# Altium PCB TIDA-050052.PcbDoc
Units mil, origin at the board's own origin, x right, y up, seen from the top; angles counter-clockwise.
Board outline 779 x 852 mil, 4 copper layers (Top Layer, Signal Layer 1, Signal Layer 2, Bottom Layer), stack 40 mil thick; 22 components, 8 nets, 35 pads, 215 vias.
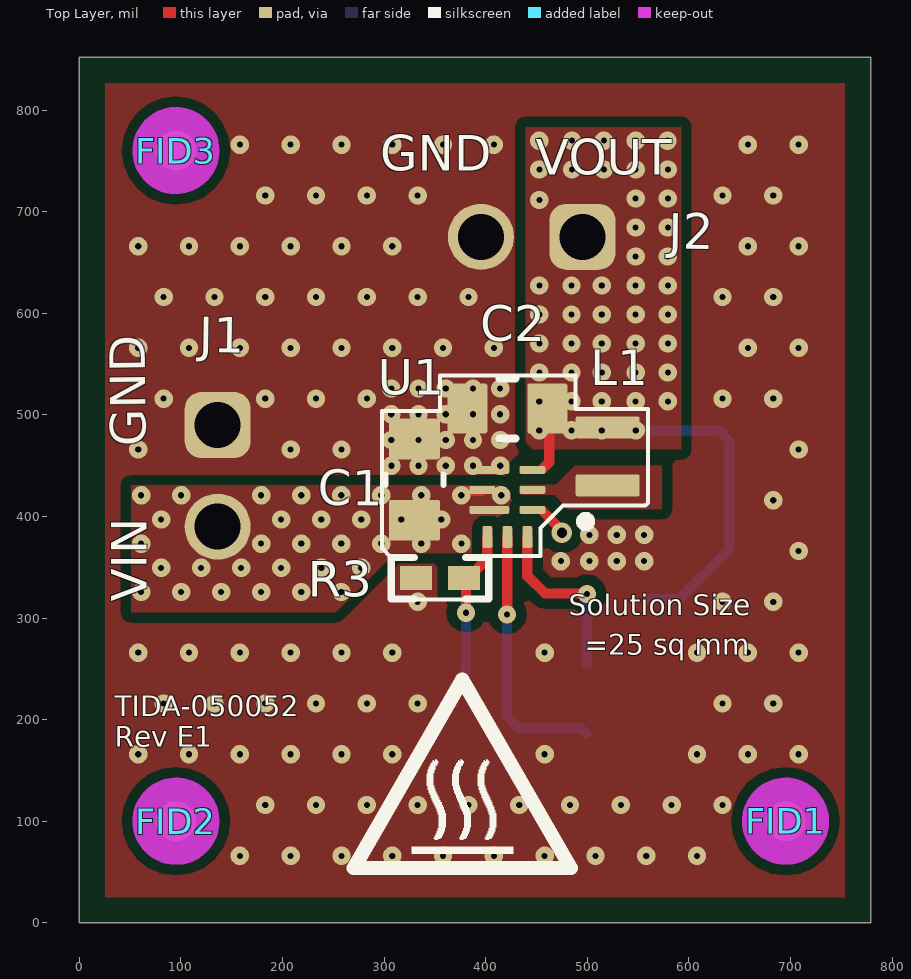
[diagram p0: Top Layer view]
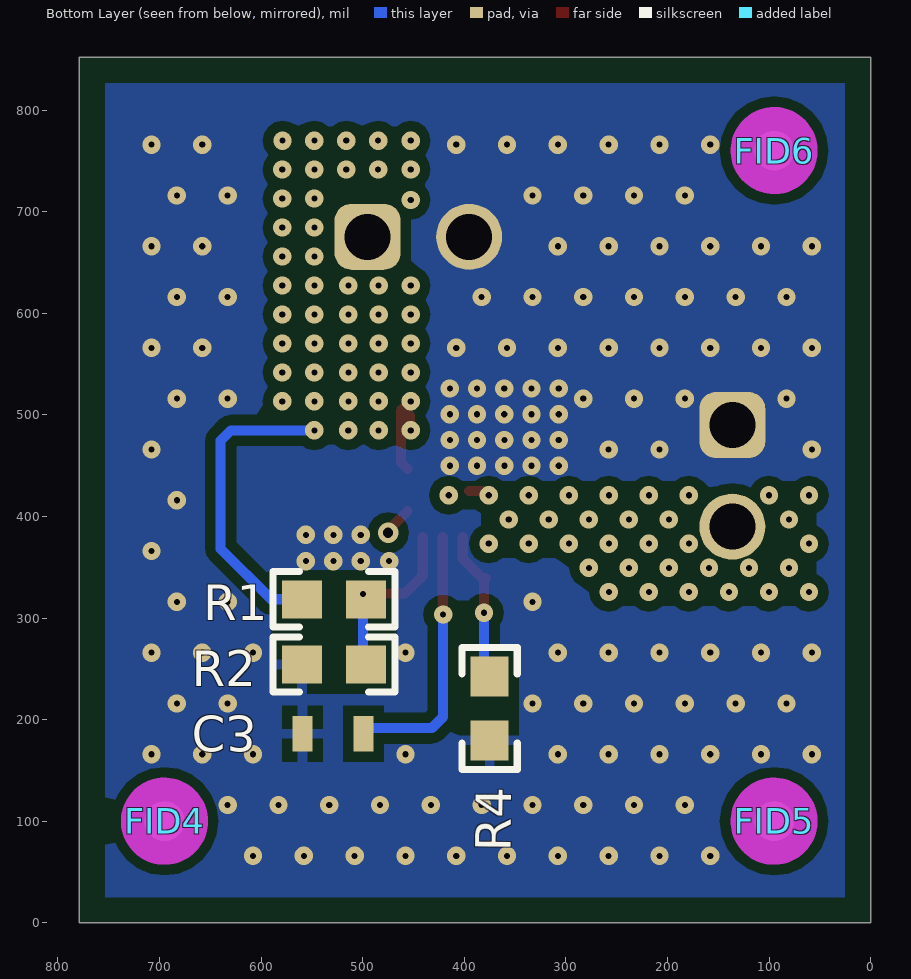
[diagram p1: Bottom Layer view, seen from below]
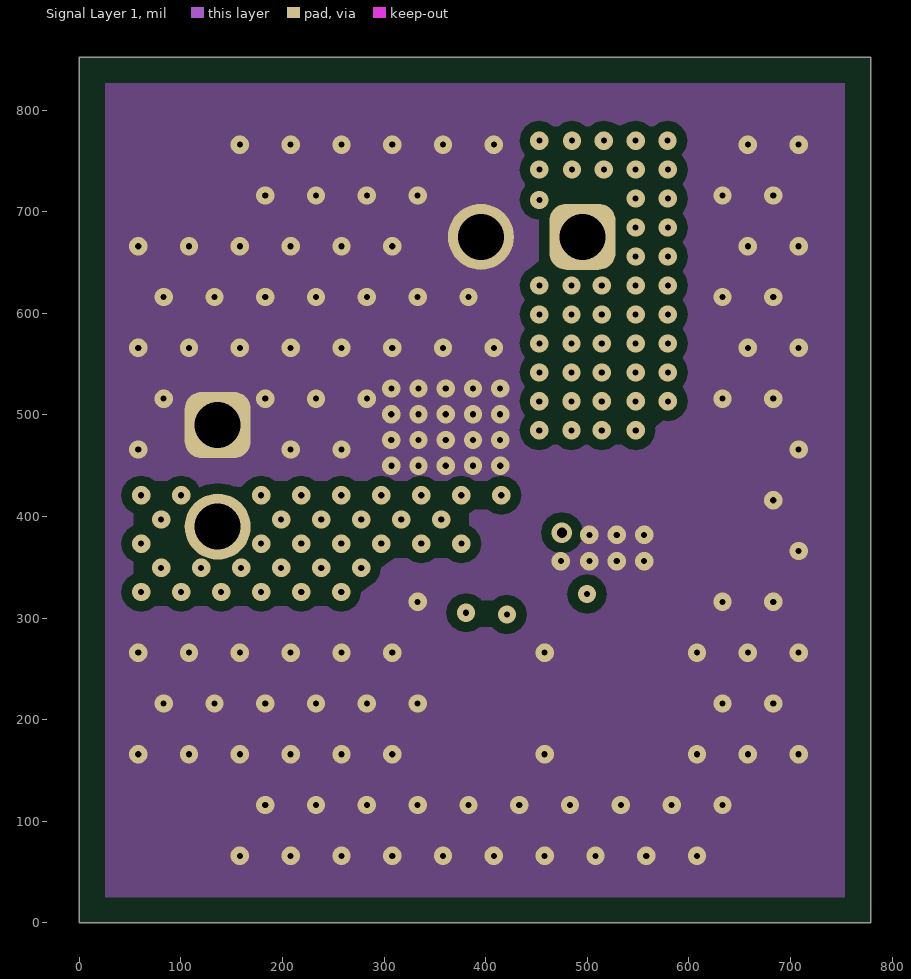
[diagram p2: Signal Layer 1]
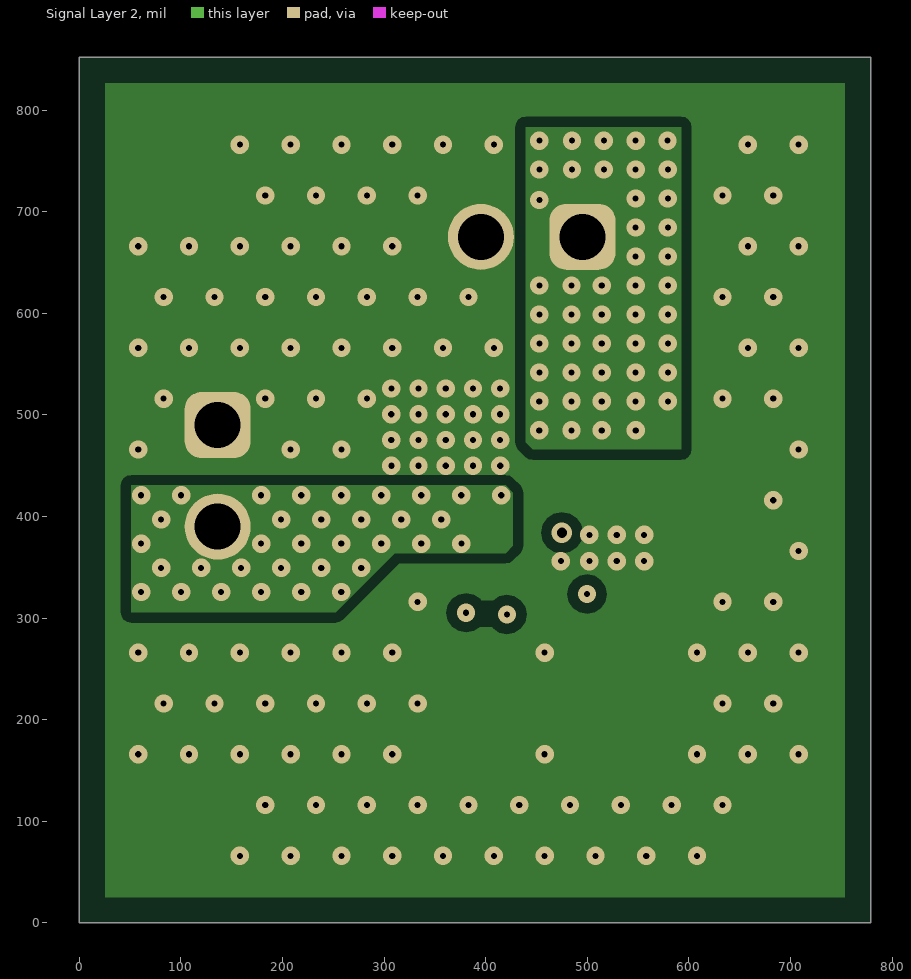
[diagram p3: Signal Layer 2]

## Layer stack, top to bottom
Top Solder: solder mask 0.4, Solder Resist, Dk 3.5
Top Layer: signal copper 1.4
Dielectric 1: prepreg 5, FR-4 High Tg, Dk 4.2
Signal Layer 1: signal copper 1.4
Dielectric 2: core 24.4, FR-4 High Tg, Dk 4.2
Signal Layer 2: signal copper 1.4
Dielectric 3: prepreg 5, FR-4 High Tg, Dk 4.2
Bottom Layer: signal copper 1.4
Bottom Solder: solder mask 0.4, Solder Resist, Dk 3.5

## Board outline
0,0 779,0 779,852 0,852

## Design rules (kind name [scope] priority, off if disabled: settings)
AcuteAngle [All] p1: minimum=4.50000000000000E+0001 checktracksonly=FALSE
AssemblyTestPointUsage [All] p1: valid=2
BoardOutlineClearance BoardOutlineClearance_MountingHoles [OnCopper and InComponentClass('Mounting Holes')] p1: gap=40 ignorepadtopadclearanceinfootprint=FALSE
BoardOutlineClearance BoardOutlineClearance_Poly [OnCopper and IsPoly] p2: gap=25 ignorepadtopadclearanceinfootprint=FALSE
BoardOutlineClearance [OnCopper and Not InComponentClass('Logo') and not InComponentClass('FiducialMark') and not InRegion(1000,500,4000,800) and not InPoly] p3: gap=40 ignorepadtopadclearanceinfootprint=FALSE
Clearance Clearance_BGA_Room [WithinRoom('BGA_Room')] p1: gap=5.9 ignorepadtopadclearanceinfootprint=FALSE
Clearance Clearance_Keepouts [((IsTrack Or IsArc) And Not InPoly) And IsFree and IsKeepOut vs ((IsTrack Or IsArc) And Not InPoly) And IsFree and IsKeepOut] p2: gap=0 ignorepadtopadclearanceinfootprint=FALSE
Clearance Clearance_Poly [InPolygon] p3: gap=10 ignorepadtopadclearanceinfootprint=FALSE
Clearance Clearance_FiducialMark [IsKeepOut and InComponentClass('FiducialMark') vs IsPad and InComponentClass('FiducialMark')] p4: gap=0 ignorepadtopadclearanceinfootprint=FALSE
Clearance [All] p5: gap=7.87 ignorepadtopadclearanceinfootprint=FALSE
ComponentClearance ComponentClearance_MountingHoles_FiducialMarks [InComponentClass('Mounting Holes') vs InComponentClass('FiducialMark')] p1: gap=50 collisioncheckmode=3 verticalgap=10 showdistances=FALSE
ComponentClearance ComponentClearance_Shunt [InComponentClass('Header') vs InComponentClass('Shunt')] p2: gap=0 collisioncheckmode=3 verticalgap=0 showdistances=FALSE
ComponentClearance ComponentClearance_Logo [InComponentClass('Logo')] p3: gap=30 collisioncheckmode=3 verticalgap=10 showdistances=FALSE
ComponentClearance ComponentClearance_ScrewToNut [(HasFootprint('NY PMS 440 0025 PH')) vs (HasFootprint('Keystone_1902C'))] p4: gap=5 collisioncheckmode=3 verticalgap=10 showdistances=FALSE
ComponentClearance ComponentClearance_MountingHoles [InComponentClass('Mounting Holes')] p5: gap=100 collisioncheckmode=3 verticalgap=100000 showdistances=FALSE
ComponentClearance ComponentClearance_SmallPassives [HasFootprint('0201*') or HasFootprint('0402*') or HasFootprint('0508') or HasFootprint('0603*') or HasFootprint('0612') or HasFootprint('0805*') or HasFootprint('0815*') or HasFootprint('0830*') or HasFootprint('1206*') or HasFootprint('1210*') or HasFootprint('1808*') or HasFootprint('1812*') or HasFootprint('1825*') or HasFootprint('2010*') or HasFootprint('2220*') or HasFootprint('2225*') or HasFootprint('2512*') or HasFootprint('2728*') or HasFootprint('3518*') vs HasFootprint('0201*') or HasFootprint('0402*') or HasFootprint('0508') or HasFootprint('0603*') or HasFootprint('0612') or HasFootprint('0805*') or HasFootprint('0815*') or HasFootprint('0830*') or HasFootprint('1206*') or HasFootprint('1210*') or HasFootprint('1808*') or HasFootprint('1812*') or HasFootprint('1825*') or HasFootprint('2010*') or HasFootprint('2220*') or HasFootprint('2225*') or HasFootprint('2512*') or HasFootprint('2728*') or HasFootprint('3518*')] p6: gap=14.96 collisioncheckmode=3 verticalgap=10 showdistances=FALSE
ComponentClearance ComponentClearance_THtoSMT [IsThruComponent vs IsSMTComponent] p7: gap=30 collisioncheckmode=3 verticalgap=30 showdistances=FALSE
ComponentClearance ComponentClearance_THtoTH [IsThruComponent vs IsThruComponent] p8: gap=30 collisioncheckmode=3 verticalgap=30 showdistances=FALSE
ComponentClearance [All] p9: gap=20 collisioncheckmode=3 verticalgap=10 showdistances=FALSE
DiffPairsRouting [All] p1: maxlimit=100 minlimit=10 mostfreqgap=10 toplayer_minwidth=15 toplayer_maxwidth=15 toplayer_prefwidth=15 midlayer1_minwidth=15 midlayer1_maxwidth=15 midlayer1_prefwidth=15 midlayer2_minwidth=15 midlayer2_maxwidth=15 midlayer2_prefwidth=15 bottomlayer_minwidth=15 bottomlayer_maxwidth=15 bottomlayer_prefwidth=15 maxuncoupledlength=1000
FabricationTestPointUsage TestPointUsage [All] p1: valid=2 allowmultiple=FALSE
FabricationTestpoint Testpoint [All] p1: side=3 testpointundercomponent=TRUE minsize=40 maxsize=100 preferedsize=60 minholesize=0 maxholesize=40 preferedholesize=32 testpointgrid=1 allowsidetop=TRUE allowsidebottom=TRUE usegrid=TRUE gridtolerance=0.01
FanoutControl Fanout_LCC [IsLCC] p1: bgadir=Out bgaviamode=Centered fanoutstyle=Auto fanoutdirection=Alternating viagrid=1 // Fanout_LCC (Default Rule)
FanoutControl Fanout_BGA [IsBGA] p2: bgadir=Out bgaviamode=Centered fanoutstyle=Auto fanoutdirection=Alternating viagrid=1 // Fanout_BGA (Default Rule)
FanoutControl Fanout_Default [All] p4: bgadir=Out bgaviamode=Centered fanoutstyle=Auto fanoutdirection=Alternating viagrid=1 // Fanout_Default (Default Rule)
FanoutControl Fanout_Small [(CompPinCount < 5)] p5: bgadir=Out bgaviamode=Centered fanoutstyle=Auto fanoutdirection=OutThenIn viagrid=1 // Fanout_Small (Default Rule)
HoleSize [All] p1: absolutevalues=TRUE maxlimit=251 minlimit=5.9 maxpercent=80.000 minpercent=20.000
MinimumAnnularRing MinimumAnnularRing_ThermalPadVias [IsVia and InAnyComponent] p1: minimumring=5.91
MinimumAnnularRing [All] p2: minimumring=5
MinimumSolderMaskSliver MinimumSolderMaskSliver_Logo [InComponentClass('Logo') vs InComponentClass('Logo')] p1: minsoldermaskwidth=0.7
MinimumSolderMaskSliver [All] p2: minsoldermaskwidth=3.94
PlaneConnect [All] p1: planeconnectstyle=Relief reliefexpansion=10 reliefentries=4 reliefconductorwidth=10 reliefairgap=10
PolygonConnect PolygonConnect_R2 [InComponent('R4') or InComponent('C3') or InComponent('R2') or InComponent('R6') or InComponent('R8')] p1: connectstyle=Relief reliefconductorwidth=10 reliefentries=4 polygonreliefangle="90 Angle" airgapwidth=10
PolygonConnect [All] p2: connectstyle=Direct reliefconductorwidth=10 reliefentries=4 polygonreliefangle="90 Angle" airgapwidth=10
RoomDefinition BGA_Room [False] p1: confinementstyle=ConfineIn formatcopy=TRUE lockcomponents=FALSE outline 1079,796 1265,796 1265,610.65 1079,610.65
RoutingVias ThermalPadVias [IsVia and InAnyComponent] p1: holewidth=7.87 width=19.68 viastyle="Through Hole" minholewidth=7.87 minwidth=19.68 maxholewidth=12.99 maxwidth=23.62
RoutingVias [All] p2: holewidth=16 width=34 viastyle="Through Hole" minholewidth=5.9 minwidth=18 maxholewidth=40 maxwidth=65
SilkToBoardRegionClearance [Not ((IsComment or IsDesignator) And (Hide <> 'False')) and not InRegion(1000,500,4000,800)] p1:
SilkToSilkClearance SilkToSilkClearance_Pb-FreeLogo [(HasFootprint('Pb-Free_Overlay_Medium') OR HasFootprint('Pb-Free_Overlay_Small')) vs (HasFootprint('Pb-Free_Overlay_Medium') OR HasFootprint('Pb-Free_Overlay_Small'))] p1: silktosilkclearance=0
SilkToSilkClearance [All] p2: silktosilkclearance=4
SilkToSolderMaskClearance SilkToComponentPadClearance [(IsPad or IsFill or IsRegion) and InAnycomponent] p1: minsilkscreentomaskgap=5 clearancetoexposedcopper=TRUE
SilkToSolderMaskClearance "Silk to Solder Mask Opening" [All] p2: minsilkscreentomaskgap=3.94 clearancetoexposedcopper=FALSE
SolderMaskExpansion [All] p1: expansion=1.97
Width [All] p1: maxlimit=100 minlimit=6 preferedwidth=10 checkconnectedcopper=TRUE
15 further rules are at their usual default settings.

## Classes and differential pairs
component class TIDA-050052_Hardware: FID1 FID2 FID3 FID4 FID5 FID6 SH-J1 SH-J5 ZZ1 ZZ2 ZZ3 ZZ4
component class FiducialMark: FID1 FID2 FID3 FID4 FID5 FID6
component class AssemblyNote: ZZ1 ZZ2 ZZ3 ZZ4
component class TIDA-050052: C1 C2 C3 J1 J2 L1 R1 R2 R3 R4 R49 U1
component class Header: J1 J2

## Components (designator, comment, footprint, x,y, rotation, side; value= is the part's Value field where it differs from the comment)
C1 "GMC21X7R106K25NT" FP-GMC21X7R106K25NT_0805-MFG 330,436.32 r270 top value=10µF
C2 "C2012X7S1A226M125AC" 0805_HV1 421.26,506.34 r180 top value=22uF
C3 "GRM1885C1H332JA01D" 0603S 529.26,186.34 r0 bottom value=3300pF
FID1 "Fiducial" Fiducial10-20 695.13,100.14 r0 top
FID2 "Fiducial" Fiducial10-20 95.13,100.14 r0 top
FID3 "Fiducial" Fiducial10-20 95.13,760.14 r0 top
FID4 "Fiducial" Fiducial10-20 695.13,100.14 r90 bottom
FID5 "Fiducial" Fiducial10-20 95.13,100.14 r180 bottom
FID6 "Fiducial" Fiducial10-20 95.13,760.14 r180 bottom
J1 "61300211121" WURTH_61300211121 136.26,440.05 r270 top
J2 "61300211121" WURTH_61300211121 445.26,675.34 r180 top
L1 "DFE201612E-1R0M=P2" DFE201612E 520.07,459.11 r90 top value=1uH
R1 "RC0603FR-0726K1L" 0603 528.26,318.54 r0 bottom value=26.1k
R2 "RC0603JR-070RL" 0603 528.26,254.34 r180 bottom value=0
R3 "CRCW040226K1FKED" 0402 355,339.34 r0 top value=26.1k
R4 "RC0603FR-0726K1L" 0603 375.13,211.14 r90 bottom value=26.1k
U1 "TPS62903RPJR" RPJ0009A 421.26,416.34 r180 top
ZZ1 "This Assembly Note is for PCB labels only" AssemblyNoteLabel 0,2000 r0 top
ZZ2 "These assemblies are ESD sensitive, ESD precautions shall be observed." AssemblyNote 0,1900 r0 top
ZZ3 "These assemblies must be clean and free from flux and all contaminants. Use of no clean flux is not acceptable." AssemblyNote 0,1800 r0 top
ZZ4 "These assemblies must comply with workmanship standards IPC-A-610 Class 2, unless otherwise specified." AssemblyNote 0,1700 r0 top
? "CAUTION HOT SURFACE" IEC_HotSurface_Small 377,147 r0 top

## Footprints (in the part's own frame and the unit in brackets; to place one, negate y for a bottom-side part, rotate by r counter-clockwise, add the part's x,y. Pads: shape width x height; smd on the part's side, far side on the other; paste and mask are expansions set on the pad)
0402 [mm] "0402 from SM-752 data"
  rect 0.8x0.6 smd: 1(-0.6,0) 2(0.6,0)
  silkscreen extent -1.22,-0.52 1.22,0.52, body extent -0.55,-0.3 0.55,0.3, height 0.6
0603 [mm] "0603 from SM-752 data"
  rect 1x0.95 smd: 1(-0.8,0) 2(0.8,0)
  silkscreen extent -1.52,-0.69 1.52,0.69, body extent -0.87,-0.47 0.87,0.47, height 1
0603S [mil]
  rect 20x35 smd: 1(-30,0) 2(30,0)
  body extent -34,-19 34,19, height 39
0805_HV1 [mm] "Custom footprint based on analyzing multiple manufacturer recommendations"
  rrect10% 1x1.25 smd: 1(-1,0) 2(1,0)
  silkscreen extent -0.2,-0.75 0.2,0.75, body extent -1.1,-0.72 1.1,0.73, height 1.45
AssemblyNote [mil] "Assembly Note"
AssemblyNoteLabel [mil] "Assembly Note for PCB Labels"
DFE201612E [mm] "MuRata recommended"
  rrect18% 0.55x1.6 smd: 1(-0.725,0) 2(0.725,0)
  body extent -1.1,-0.9 1.1,0.9, height 1.2
Fiducial10-20 [mm]
  round 1 smd mask+0.5: 1(0,0)
  Top Layer keep-out circle w1.178: c0,0 r0.5
FP-GMC21X7R106K25NT_0805-MFG [mil]
  rrect10% 40x50 smd paste+0 mask+0: 1(-40,0) 2(40,0)
  silkscreen extent -5,-29 5,29, body extent -64,-32 64,32, height 10
IEC_HotSurface_Small [mil]
  silkscreen extent -107,-93 107,92
RPJ0009A [mm] "VQFN-HR-9"
  rrect50% 0.65x0.2 smd: 1(-0.625,0.25) 2(-0.625,-0.25) 3(-0.625,-0.75) 5(0.625,-0.25)
  rrect50% 1x0.2 smd: 4(0.45,-0.75) 6(0.45,0.25)
  rrect40% 0.25x0.55 smd: 7(0.5,0.925) 8(0,0.925) 9(-0.5,0.925)
  body extent -0.8,-1.05 0.8,1.05, height 1
WURTH_61300211121 [mm] "Header, 2.54mm, 2x1, TH"
  rrect50% 1.65x1.65 hole 1.15: 1(-1.27,0)
  round 1.65 hole 1.15: 2(1.27,0)
  body extent -2.54,-1.27 2.54,1.27, height 8.54

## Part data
C1: library part CMP-0092369-1, "CAP0805 X7R 10UF 10% 25V", Manufacturer="Cal-Chip Electronics", Operating Temperature Range="-55°C to +125°C", TempCo=15%, Temperature Characteristic=X7R, Tolerance_%=10%, ValueDisplayed=10uF
C2: library part CMP-0007890-2, "CAP, CERM, 22 uF, 10 V, +/- 20%, X7S, 0805", Cap_Case=0805, Manufacturer=TDK, Supplier Part Number 1=445-14560-1-ND, TempCo=X7S, Tolerance_%=20%, Value1="0.00205 ohm", Value2=10V, ValueDisplayed=22uF
C3: library part CMP-0007210-4, "CAP, CERM, 3300 pF, 50 V, +/- 5%, C0G/NP0, 0603", Cap_Case=0603, Manufacturer=MuRata, Supplier Part Number 1=GRM1885C1H332JA01D-ND, TempCo=C0G/NP0, Tolerance_%=5%, Value1=Unknown, Value2=50V, ValueDisplayed=3300pF
FID1 FID2 FID3 FID4 FID5 FID6: library part CMP-0077181-1, "Fiducial mark.  There is nothing to buy or mount.", Manufacturer=N/A
J1 J2: library part CMP-0054794-2, "Header, 2.54 mm, 2x1, Gold, TH", Color=Black, Manufacturer="Wurth Elektronik", Supplier Part Number 1=732-5315-ND
L1: library part CMP-0080773-1, "Inductor, Shielded, Metal Composite, 1 µH, 2.9 A, 0.048 ohm, SMD", Manufacturer=MuRata, PartNumber=DFE201612E-1R0M{}P2, Value1="0.048 ohm", Value2=2.9A, ValueDisplayed=1µH
R1 R4: library part CMP-0022957-2, "RES, 26.1 k, 1%, 0.1 W, 0603", Manufacturer="Yageo America", Power_W=100mW, Supplier Part Number 1=311-26.1KHRCT-ND, TempCo="200 ppm/C", Tolerance_%=1%, Value2=0.1W, Value_Code=26k1, ValueDisplayed=26.1k
R2: library part CMP-0025885-1, "RES, 0, 5%, 0.1 W, 0603", Manufacturer="Yageo America", Power_W=100mW, Supplier Part Number 1=311-0.0GRCT-ND, TempCo="200 ppm/C", Tolerance_%=5%, Value2=0.1W, Value_Code=0000, ValueDisplayed=0
R3: library part CMP-0026207-1, "RES, 26.1 k, 1%, 0.063 W, 0402", Manufacturer=Vishay-Dale, Power_W=63mW, Supplier Part Number 1=541-26.1KLCT-ND, TempCo="100 ppm/C", Tolerance_%=1%, Value2=0.063W, Value_Code=26k1, ValueDisplayed=26.1k
U1: library part CMP-0084866-4, "2.9-V to 18-V, 3-A Synchronous Buck Converters, RPJ0009A (VQFN-HR-9)", Alternate Manufacturer="Texas Instruments", Alternate PartNumber=TPS62903RPJT
ZZ1: library part CMP-0003616-3
ZZ2: library part CMP-0077236-1
ZZ3: library part CMP-0077237-1
ZZ4: library part CMP-0077238-1
?: library part CMP-0074837-1, "IEC 61010-1 Hot Surface Warning"

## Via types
v1: diameter 18, hole 6, Top Layer to Bottom Layer, tented both sides, 192 vias
v2: diameter 18, hole 6.1, Top Layer to Bottom Layer, tented both sides, 22 vias
v3: diameter 20, hole 10, Top Layer to Bottom Layer, 1 vias

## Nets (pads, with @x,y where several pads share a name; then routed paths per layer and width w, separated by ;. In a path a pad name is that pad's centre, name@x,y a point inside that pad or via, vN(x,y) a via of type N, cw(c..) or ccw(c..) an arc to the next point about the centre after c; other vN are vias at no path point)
GND: C1.1 C2.2 C3.2 J1.1 J2.2 R2.1 R3.1 R4.1 U1.4
  other v1: 158,66 208,66 258,66 308,66 358,66 408,66 458,66 508,66 558,66 608,66 183,116 233,116 283,116 333,116 383,116 433,116 483,116 533,116 583,116 633,116 58,166 108,166 158,166 208,166 258,166 308,166 458,166 608,166 658,166 708,166 83,216 133,216 183,216 233,216 283,216 333,216 633,216 683,216 58,266 108,266 158,266 208,266 258,266 308,266 458,266 608,266 658,266 708,266 333,316 633,316 683,316 474,356.06 502,356.06 529,356.06 556,356.06 708,366 502,382 529,382 556,382 683,416 307.1,450 333.89,450 360.68,450 58,466 208,466 258,466 708,466 360.68,475.32 387.47,475.32 414.26,475.32 414.26,500.64 83,516 183,516 233,516 283,516 633,516 683,516 307.1,525.97 333.89,525.97 414.26,525.97 58,566 108,566 158,566 208,566 258,566 308,566 358,566 408,566 658,566 708,566 83,616 133,616 183,616 233,616 283,616 333,616 383,616 633,616 683,616 58,666 108,666 158,666 208,666 258,666 308,666 658,666 708,666 183,716 233,716 283,716 333,716 633,716 683,716 158,766 208,766 258,766 308,766 358,766 408,766 658,766 708,766
  other v2: 387.47,450 414.26,450 307.1,475.32 333.89,475.32 307.1,500.64 333.89,500.64 360.68,500.64 387.47,500.64 360.68,525.97 387.47,525.97
NetC2_1: C2.1 J2.1 L1.2 R1.2 U1.3 | length 391.2
  Top Layer w10: C2.1@453.66,484.82 453.66,499.37 C2.1 462.51,504.45 462.51,453.49 U1.3@456.04,447.02
  Bottom Layer w10: v2@547.26,484.82 v2(547.63,484.82) 629.78,484.82 639.95,474.65 639.95,368.34 590.15,318.54 R1.2
  other v1: 514.21,513.34 547.63,513.34 579.26,513.34 452.75,541.86 484.38,541.86 514.21,541.86 547.63,541.86 579.26,541.86 452.75,570.37 484.38,570.37 514.21,570.37 547.63,570.37 579.26,570.37 452.75,598.89 484.38,598.89 514.21,598.89 547.63,598.89 579.26,598.89 452.75,627.41 484.38,627.41 514.21,627.41 547.63,627.41 579.26,627.41 547.63,655.93 579.26,655.93 547.63,684.45 579.26,684.45 452.75,711.62 547.63,712.96 579.26,712.96 452.75,741.48 484.89,741.48 516.26,741.48 547.63,741.48 579.26,741.48 452.75,770 484.89,770 516.26,770 547.63,770 579,770
  other v2: 452.75,484.82 484.38,484.82 514.21,484.82 452.75,513.34 484.38,513.34
NetC3_1: C3.1 U1.8 | length 262.4
  Top Layer w10: v1(420.88,303.6) 421.26,303.98 U1.8
  Bottom Layer w10: v1(420.88,303.6) 420.88,202.95 432.08,191.75 493.84,191.75 C3.1
NetR1_1: R1.1 R2.2 U1.9 | length 165.7
  Top Layer w10: U1.9 440.94,341.73 458.34,324.34 v1@495.76,324.34
  Bottom Layer w10: R1.1 499.76,315.54 R2.2@499.76,254.34
  other v1: 499.76,323.67
NetR3_2: R3.2 R4.2 U1.7 | length 152.3
  Top Layer w10: v1(380.7,305.28) 380.7,337.26 R3.2 382.56,339.34 401.57,358.35 U1.7
  Bottom Layer w10: R4.2 380.7,248.21 v1(380.7,305.28)
PG: U1.1 | length 31
  Top Layer w10: U1.1@455.83,405.45 474,387.28 v3@474,382
  other v3: 475,384
SW: L1.1 U1.2
VIN: C1.2 J1.2 U1.5 U1.6 | length 21.3
  Top Layer w10: v2(376,420.96) 378.16,420.96 382.32,425.12 U1.5@395.59,425.12
  other v1: 60.83,325.71 100.23,325.71 139.62,325.71 179.02,325.71 218.42,325.71 257.81,325.71 80.53,349.53 119.93,349.53 159.32,349.53 198.72,349.53 238.11,349.53 277.51,349.53 60.83,373.34 179.02,373.34 218.42,373.34 257.81,373.34 297.21,373.34 376,373.34 80.53,397.15 198.72,397.15 238.11,397.15 277.51,397.15 60.83,420.96 100.23,420.96 179.02,420.96 218.42,420.96 257.81,420.96 297.21,420.96
  other v2: 336.6,373.34 316.91,397.15 356.3,397.15 336.6,420.96 415.4,420.96
pads on no net: FID1.1 FID2.1 FID3.1 FID4.1 FID5.1 FID6.1

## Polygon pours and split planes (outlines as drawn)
GND on Top Layer "TOP_LAYER_GND_P036" (solid, remove dead copper, pour order 36): 1,852.83 780,852.83 780,0.83 1,0.83
VIN on Top Layer "TOP_LAYER_VIN_P033" (solid, remove dead copper, pour order 33): 51,430.67 51,305.64 252.17,305.64 310.53,364 426.63,364 426.63,430.67
SW on Top Layer "TOP_LAYER_SW_P030" (solid, remove dead copper, pour order 30): 434.63,431.34 469.14,431.34 487.77,449.94 573.26,449.94 573.26,407.34 481.26,407.34 467.26,421.34 434.63,421.34
NetC2_1 on Top Layer "TOP_LAYER_NETC2_1_P032" (solid, remove dead copper, pour order 32): 592.26,466 592.26,783.34 439.26,783.34 439.26,508.34 439.26,466
GND on Signal Layer 2 "SIGNAL_LAYER_2_GND_P046" (solid, remove dead copper, pour order 46): 0,852 779,852 779,2.34 0,2.34
VIN on Signal Layer 2 "SIGNAL_LAYER_2_VIN_P044" (solid, remove dead copper, pour order 44): 252.17,305.64 310.53,364 426.63,364 426.63,430.67 51,430.67 51,305.64
NetC2_1 on Signal Layer 2 "SIGNAL_LAYER_2_NETC2_1_P042" (solid, remove dead copper, pour order 42): 446.33,466 592.26,466 592.26,783.34 439.26,783.34 439.26,473.07
GND on Bottom Layer "BOTTOM_LAYER_GND_P050" (solid, remove dead copper, pour order 50): 0.26,852 779,852 779,0 0.26,0
GND on Signal Layer 1 "SIGNAL_LAYER_1_GND_P040" (solid, remove dead copper, pour order 40): 1,852.83 780,852.83 780,2.16 1,2.17

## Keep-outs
Keep-Out Layer:
  text ".Layer_Name" at 577,-858.49 h60

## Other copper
Top Layer:
  pour cut-out: 329.36,462.34
  pour cut-out: 483.26,332.34
  pour cut-out: 642.36,452.34
  pour cut-out: 571.73,464 571.73,450.34 570.26,450.34 565.59,450.34 534.73,450.34 534.73,464
  pour cut-out: 624.26,457.34
  pour cut-out: 527.26,339.34
  text ".Layer_Name" at 577,-858.49 h60
Signal Layer 1:
  text ".Layer_Name" at 577,-857.49 h60
Signal Layer 2:
  text ".Layer_Name" at 577,-857.49 h60
Bottom Layer:
  text ".Layer_Name" at 577,-858.49 h60

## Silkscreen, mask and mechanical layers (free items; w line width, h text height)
Top Overlay:
  circle w10: c498.27,395.1 r4.47
  lines w4: 307,359.84 298,368.84 298,503.7 355,503.7 355,539 488.26,539 488.26,506 559.54,506 559.54,430.99 559.54,413.38 557.03,410.87 476.14,410.87 454,388.73 454,361 403,361 403,338.6 403,318.21 396.45,318.21 309.02,318.21
  text "GND" at 296.13,740.14 h35
  text "VOUT" at 449.26,736.34 h35
  text "GND" at 65.99,469.14 h35 r90.77
  text "VIN" at 66.26,316.34 h35 r90
  text "Solution Size" at 481.68,303 h20
  text "=25 sq mm" at 497.26,264.14 h20
  text "TIDA-050052 / Rev E1" at 35,173.48 h20
  text ".Layer_Name" at 577,-858.49 h60
Bottom Overlay:
  text ".Layer_Name" at 577,-858.49 h60
Top Paste:
  text ".Layer_Name" at 577,-858.49 h60
Bottom Paste:
  text ".Layer_Name" at 577,-858.49 h60
Top Solder:
  text ".Layer_Name" at 577,-858.49 h60
  text ".Layer_Name" at 577,-858.49 h60
Bottom Solder:
  text ".Layer_Name" at 577,-858.49 h60
Drill Guide:
  text ".Layer_Name" at 577,-858.49 h60
M1 Board Outline:
  lines w10: -5,0 ccw(c0,0) 0,-5 ; -5,0 ccw(c0,0) 0,-5 ; -5,0 -5,852 ; -5,852 cw(c0,852) 0,857 ; -5,852 cw(c0,852) 0,857 ; 0,-5 779,-5 ; 0,857 779,857 ; 779,-5 ccw(c779,0) 784,0 ; 779,-5 ccw(c779,0) 784,0 ; 779,857 cw(c779,852) 784,852 ; 779,857 cw(c779,852) 784,852 ; 784,0 784,852 ; 5,5 774,5 774,847 5,847 5,5 ; 26.23,31 752.77,31 752.77,822 26.23,822 26.23,31
  text ".Layer_Name" at 577,-858.49 h60
M2 Board Dimensions:
  rectangle: 0,-275 125,-150
  rectangle: 125,-400 500,-275
  lines w7: 0,-275 1000,-275 ; 125,-400 125,-150 ; 250,-400 250,-150 ; 500,-400 500,-150 ; 750,-400 750,-150 ; 0,-400 1000,-400 1000,-150 0,-150 0,-400
  text ".Layer_Name" at 577,-858.49 h60
M3 3D STEP Top:
  text ".Layer_Name" at 577,-858.49 h60
M4 3D STEP Bottom:
  text ".Layer_Name" at 577,-858.49 h60
M5 Assembly Top:
  lines w10: -292,-930.17 6308,-930.17 ; -292,-726.83 6310,-726.83 ; -292,-523.5 -292,-1133.5 3713,-1133.5 6310,-1133.5 6310,-523.5 -291.5,-523.5 -291.5,-1133.5 1284,-1133.5 ; 2173,-1133.5 2173,-523.5 ; 3440,-726.83 3440,-523.5 ; 4280,-726.83 4280,-523.5 ; 4902,-1140 4902,-937.17
  text "COMPONENTS MARKED 'DNP' SHOULD NOT BE POPULATED." at 1153.5,-318.5 h60
  text "ASSEMBLY VARIANT:" at 1153,-434 h60
  text ".VariantName" at 2189,-434 h60
  text "PCB VIEWED FROM TOP SIDE" at -228.5,-655.67 h60
  text "BOARD #:" at 2248,-655.67 h60
  text ".PRJ_Number" at 2793.5,-655.67 h60
  text "REV:" at 3638,-655.67 h60
  text ".PCB_Rev" at 3929.5,-655.67 h60
  text "SVN REV:" at 4476,-655.67 h60
  text ".VersionControl_RevNumber" at 4982,-655.67 h60
  text "TID #:" at 2248,-859 h60
  text ".TID" at 2793.5,-859 h60
  text "PLOT NAME =" at -228.5,-1064.34 h60
  text ".plot_File_Name" at 577,-1064.34 h60
  text "GENERATED    :" at 2250,-1064.34 h60
  text ".Print_Date" at 3119.5,-1064.34 h60
  text ".Print_Time" at 3848.5,-1064.34 h60
  text "TEXAS INSTRUMENTS" at 5113,-1064.34 h60
M6 Assembly Bottom:
  lines w10: -292.5,-727.33 6309.5,-727.33 ; -290.5,-930.67 6309.5,-930.67 ; 1115.5,-1140.5 1115.5,-937.67 ; 1737.5,-727.33 1737.5,-524 ; 2577.5,-727.33 2577.5,-524 ; 3844.5,-1134 3844.5,-524 ; 4733.5,-1134 6309,-1134 6309,-524 -292.5,-524 -292.5,-1134 2304.5,-1134 6309.5,-1134 6309.5,-524
  text "COMPONENTS MARKED 'DNP' SHOULD NOT BE POPULATED." at 6102,-318 h60
  text ".VariantName" at 5058,-434 h60
  text "ASSEMBLY VARIANT:" at 6097,-434 h60
  text ".VersionControl_RevNumber" at 1035.5,-656.17 h60
  text "SVN REV:" at 1541.5,-656.17 h60
  text ".PCB_Rev" at 2088,-656.17 h60
  text "REV:" at 2379.5,-656.17 h60
  text ".PRJ_Number" at 3224,-656.17 h60
  text "BOARD #:" at 3769.5,-656.17 h60
  text "PCB VIEWED FROM BOTTOM SIDE" at 6246,-656.17 h60
  text ".TID" at 3224,-859.5 h60
  text "TID #:" at 3769.5,-859.5 h60
  text "TEXAS INSTRUMENTS" at 904.5,-1064.84 h60
  text ".Print_Time" at 2169,-1064.84 h60
  text ".Print_Date" at 2898,-1064.84 h60
  text "GENERATED    :" at 3767.5,-1064.84 h60
  text ".plot_File_Name" at 5440.5,-1064.84 h60
  text "PLOT NAME =" at 6246,-1064.84 h60
M9 Title Sheet:
  drawing of 57 lines, arcs and shapes, not listed
  text "1" at 739.84,8036.5 h70
  text "2" at 3235.5,8036.5 h70
  text "3" at 5724.84,8036.5 h70
  text "4" at 8231.51,8036.5 h70
  text "5" at 10730.5,8036.5 h70
  text "6" at 13235.5,8036.5 h70
  text "A" at -416.5,6893.5 h70
  text "A" at 14383.5,6893.5 h70
  text "B" at -416.5,4513.5 h70
  text "B" at 14383.5,4513.5 h70
  text "C" at -416.5,2138.5 h70
  text "C" at 14383.5,2138.5 h70
  text "PROJECT TITLE:" at 11343.5,277.5 h45
  text ".PRJ_Title" at 11393.5,144.17 h70
  text "DESIGNED FOR:" at 11343.5,-23.5 h45
  text ".PRJ_Customer" at 11393.5,-163.5 h70
  text "D" at -416.5,-231.5 h70
  text "D" at 14383.5,-231.5 h70
  text "FILE NAME:" at 11343.5,-323.5 h45
  text ".PCB_File_Name_No_Path" at 11393.5,-443.5 h70
  text "Texas Instruments (TI) and/or its licensors do not warrant the accuracy or completeness of this specification" at 6374,-605.34 h45
  text "ENGINEER:" at 11343.5,-613.5 h45
  text "LAYOUT BY:" at 12848.5,-613.5 h45
  text "or any information contained therein. TI and/or its licensors do not warrant that this design will meet" at 6329.01,-718 h45
  text ".PRJ_Engineer" at 11393.5,-768.49 h70
  text ".PCB_Layout" at 12899,-768.49 h70
  text "the specifications, will be suitable for your application or fit for any particular purpose, or will operate in" at 6329.01,-830.67 h45
  text ".Layer_Name" at 577,-858.49 h60
  text "ALTIUM DESIGNER VERSION:" at 12848.5,-923.5 h45
  text "an implementation. TI and/or its licensors do not warrant that the design is production worthy. You should" at 6329.01,-943.33 h45
  text "completely validate and test your design implementation to confirm the system functionality for your application." at 6374,-1056 h45
  text ".print_Scale" at 11393.5,-1056.83 h70
  text ".Application_BuildNumber" at 12899,-1056.83 h70
  text "1" at 739.84,-1263.5 h70
  text "2" at 3235.5,-1263.5 h70
  text "3" at 5724.84,-1263.5 h70
  text "4" at 8231.51,-1263.5 h70
  text "5" at 10730.5,-1263.5 h70
  text "6" at 13235.5,-1263.5 h70
M10 Fab Notes:
  drawing of 189 lines, arcs and shapes, not listed
  text "DESIGN INFORMATION" at 12382.02,6356.17 h60
  text "MIN. TRACK WIDTH:" at 11737.46,6224.05 h60
  text "10" at 12833.7,6224.05 h60
  text "MIL" at 12988.46,6224.05 h60
  text "MIN. CLEARANCE:" at 11737.46,6099.92 h60
  text "5.9" at 12773.7,6099.93 h60
  text "MIL" at 12988.46,6099.92 h60
  text "MIN. VIA PAD SIZE:" at 11737.46,5975.8 h60
  text "18" at 12803.71,5975.8 h60
  text "MIL" at 12988.46,5975.8 h60
  text "0.05mm (2MIL)" at 12432.46,5845.9 h60
  text "MINIMUM ANNULAR RING" at 11408.23,5837.67 h60
  text "EXTERNAL" at 13140.46,5837.67 h60
  text "PER" at 11608.23,5727.55 h60
  text "IPC-D-275 CLASS 2 LEVEL C" at 11828.23,5727.54 h60
  text "MIL, HOLES" at 13316.46,5627.07 h60
  text "+/-" at 12924,5618.48 h60
  text "+/-" at 13778,5618.48 h60
  text "REGISTRATION TOLERANCES:" at 11408.23,5617.42 h60
  text "METAL" at 12608,5617.42 h60
  text "5" at 13184.2,5617.42 h60
  text "3" at 14017.2,5617.42 h60
  text "MIL" at 14133.46,5617.42 h60
  text "HOLE SIZE TOLERANCE (UNLESS OTHERWISE SPECIFIED):" at 11408.23,5519.1 h60
  text "+/-" at 13778,5516.23 h60
  text "3" at 14017.2,5515.17 h60
  text "MIL" at 14133.46,5515.17 h60
  text "MATERIAL:" at 11333.46,5377.52 h60
  text "FR-4 High Tg" at 12319.9,5249 h60
  text "X" at 12175.46,5241.01 h60
  text "FR-408" at 11754.46,5236.49 h60
  text "OTHER" at 13242.46,5236.49 h60
  text "40 MIL (1.0mm) +/-10%" at 12074.56,5093.46 h60
  text "X" at 11954.46,5091.01 h60
  text "THICKNESS:" at 11408.23,5085.24 h60
  text "OTHER" at 13359.46,5085.24 h60
  text "TOLERANCE:" at 11408.23,4946.92 h60
  text "X" at 12256.46,4946.92 h60
  text "ANSI IPC-6012 TYPE 3 CLASS 2" at 12434.48,4946.92 h60
  text "OTHER +/-" at 12434.46,4802.73 h60
  text "BOW & TWIST:" at 11408.23,4657.54 h60
  text "X" at 12256.46,4657.54 h60
  text "ANSI IPC-6012 TYPE 3 CLASS 2" at 12434.48,4657.54 h60
  text "OTHER +/-" at 12434.46,4510.85 h60
  text "DRILLING:" at 11333.46,4380.23 h60
  text "NC_DRILL FILES" at 13094.46,4275.04 h60
  text "REFERENCE:" at 11408.23,4271.1 h60
  text "X" at 12065.46,4271.01 h60
  text "AS SHOWN" at 12243.46,4271.1 h60
  text "X" at 12966.46,4271.1 h60
  text "OTHER" at 13392.46,4128.85 h60
  text "PTH COPPER THICKNESS:" at 11407.91,4125.32 h60
  text "X" at 12547.14,4125.32 h60
  text "20-30 um" at 12675.14,4125.32 h60
  text "BOARD FINISH:" at 11333.46,3977.73 h60
  text "SILKSCREEN:" at 11488.68,3867.6 h60
  text "X" at 12446.46,3867.6 h60
  text "TOP" at 12563.46,3867.6 h60
  text "BOTTOM" at 13074.46,3867.6 h60
  text "SILKSCREEN COLOR:" at 11488.68,3712.41 h60
  text "X" at 12445.46,3712.41 h60
  text "WHITE" at 12563.46,3712.41 h60
  text "OTHER" at 13074.46,3712.41 h60
  text "X" at 12576.46,3568.96 h60
  text "GREEN" at 12694.46,3568.96 h60
  text "OTHER" at 13312.46,3568.96 h60
  text "SOLDER RESIST COLOR:" at 11488.68,3562.1 h60
  text "X" at 12576.46,3414.71 h60
  text "MATTE" at 12694.46,3414.71 h60
  text "SEMI-GLOSS" at 13312,3414.07 h60
  text "IMMERSION GOLD (ENIG)" at 12394.46,3241.94 h60
  text "ENEPIG" at 13732,3234.72 h60
  text "SURFACE FINISH:" at 11333.46,3233.72 h60
  text "X" at 12216.46,3233.72 h60
  text "IMM. TIN/SILVER OR EQUIV" at 11663,3096.4 h60
  text "OTHER" at 13094.46,3092.47 h60
  text "ARRAY/PANEL:" at 11333.46,2937.09 h60
  text "CUT AND TRIM PER M1 BOARD OUTLINE" at 12394.46,2928.87 h60
  text "N.C. ROUTE" at 12394.46,2792.9 h60
  text "X" at 13082.46,2792.9 h60
  text "V. SCORE" at 13260.46,2792.9 h60
  text "CERTIFICATION:" at 11333.46,2663.77 h60
  text "MATERIALS AND WORKMANSHIP FOR ALL PCBS" at 12058.46,2663.77 h60
  text "TO MEET OR EXCEED THE REQUIREMENTS OF:" at 12058.46,2569.71 h60
  text "X" at 11695.97,2441.08 h60
  text "ANSI IPC-A-600F CLASS ->" at 11823.96,2441.08 h60
  text "X" at 13471.97,2441.08 h60
  text "2" at 13581.96,2441.08 h60
  text "1" at 13266.96,2439.58 h60
  text "3" at 13935.96,2439.58 h60
  text "X" at 12507.97,2293.39 h60
  text "RoHS" at 12635.96,2293.39 h60
  text "OTHER" at 13280.36,2293.39 h60
  text "PER ORDER" at 13677.42,2293.39 h60
  text "ALL BOARDS MUST MEET OR EXCEED UL94-V0 REQUIREMENTS." at 11361,2139.57 h60
  text "PCB MUST BEAR THE UL94V-0 UL REGISTERED MATERIAL ID NUMBER" at 11361,2023.5 h60
  text "ADDITIONAL REQUIREMENTS:" at 11333.46,1854.08 h60
  text "MICROSECTION:" at 11408.23,1746.95 h60
  text "YES" at 12313.96,1746.95 h60
  text "REQUIRED" at 13175.46,1602.62 h60
  text "BARE BOARD ELEC. TEST:" at 11408.23,1599.76 h60
  text "NONE" at 12713.96,1599.76 h60
  text "X" at 13057.46,1599.76 h60
  text "PER ORDER" at 13767.46,1599.76 h60
  text "X" at 11466.46,1446.76 h60
  text "6.1MIL VIAS REQUIRE NON-CONDUCTIVE FILL AND PLANARIZE" at 11576.38,1394.82 h59
  text "XX MIL VIAS REQUIRE CONDUCTIVE FILL AND PLANARIZE" at 11584.38,1290.84 h60
  text "OUTER XX MIL TRACES REQUIRE 50 OHM SINGLE-ENDED IMPEDANCE" at 11583.39,1127.46 h58
  text "LAYER 2 & 3 (INNER LAYERS) XX MIL WIDE, XX MIL SPACE / TRACES REQUIRE 100 OHM DIFFERENTIAL IMPEDANCE" at 11575.39,891.74 h60
  text ".Layer_Name" at 577,-858.49 h60
M11 Gerber Information:
  lines w10: -292,-930.17 6308,-930.17 ; -292,-726.83 6310,-726.83 ; -292,-523.5 -292,-1133.5 3713,-1133.5 6310,-1133.5 6310,-523.5 -291.5,-523.5 -291.5,-1133.5 1284,-1133.5 ; 2173,-1133.5 2173,-523.5 ; 3440,-726.83 3440,-523.5 ; 4280,-726.83 4280,-523.5 ; 4902,-1140 4902,-937.17
  text "ALL ARTWORK VIEWED FROM TOP SIDE" at -228.5,-655.67 h60
  text "BOARD #:" at 2248,-655.67 h60
  text ".PRJ_Number" at 2793.5,-655.67 h60
  text "REV:" at 3638,-655.67 h60
  text ".PCB_Rev" at 3929.5,-655.67 h60
  text "SVN REV:" at 4476,-655.67 h60
  text ".VersionControl_RevNumber" at 4982,-655.67 h60
  text "LAYER NAME =" at -228.5,-858.49 h60
  text "TID #:" at 2248,-859 h60
  text ".TID" at 2793.5,-859 h60
  text "PLOT NAME =" at -228.5,-1064.34 h60
  text ".plot_File_Name" at 577,-1064.34 h60
  text "GENERATED    :" at 2250,-1064.34 h60
  text ".Print_Date" at 3119.5,-1064.34 h60
  text ".Print_Time" at 3848.5,-1064.34 h60
  text "TEXAS INSTRUMENTS" at 5113,-1064.34 h60
M12 Stackup:
  drawing of 295 lines, arcs and shapes, not listed
  text "Layer" at 9793.09,7042 h60
  text "Name" at 10203,7042 h60
  text "Material" at 11142.74,7042 h60
  text "Thickness" at 12002.51,7042 h60
  text "Constant" at 12652.34,7042 h60
  text "Board Layer Stack" at 13222.2,7042 h60
  text "1" at 9793.09,6922 h60
  text "Top Overlay" at 10203,6922 h60
  text "2" at 9793.09,6802 h60
  text "Top Solder" at 10203,6802 h60
  text "Solder Resist" at 11142.74,6802 h60
  text "0.40mil" at 12002.51,6802 h60
  text "3.5" at 12652.34,6802 h60
  text "3" at 9793.09,6682 h60
  text "Top Layer" at 10203,6682 h60
  text "Copper" at 11142.74,6682 h60
  text "1.40mil" at 12002.51,6682 h60
  text "4" at 9793.09,6562 h60
  text "Dielectric 1" at 10203,6562 h60
  text "FR-4 High Tg" at 11142.74,6562 h60
  text "5.00mil" at 12002.51,6562 h60
  text "4.2" at 12652.34,6562 h60
  text "5" at 9793.09,6442 h60
  text "Signal Layer 1" at 10203,6442 h60
  text "Copper" at 11142.74,6442 h60
  text "1.40mil" at 12002.51,6442 h60
  text "6" at 9793.09,6322 h60
  text "Dielectric 2" at 10203,6322 h60
  text "FR-4 High Tg" at 11142.74,6322 h60
  text "24.40mil" at 12002.51,6322 h60
  text "4.2" at 12652.34,6322 h60
  text "7" at 9793.09,6202 h60
  text "Signal Layer 2" at 10203,6202 h60
  text "Copper" at 11142.74,6202 h60
  text "1.40mil" at 12002.51,6202 h60
  text "8" at 9793.09,6082 h60
  text "Dielectric 3" at 10203,6082 h60
  text "FR-4 High Tg" at 11142.74,6082 h60
  text "5.00mil" at 12002.51,6082 h60
  text "4.2" at 12652.34,6082 h60
  text "9" at 9793.09,5962 h60
  text "Bottom Layer" at 10203,5962 h60
  text "Copper" at 11142.74,5962 h60
  text "1.40mil" at 12002.51,5962 h60
  text "10" at 9793.09,5842 h60
  text "Bottom Solder" at 10203,5842 h60
  text "Solder Resist" at 11142.74,5842 h60
  text "0.40mil" at 12002.51,5842 h60
  text "3.5" at 12652.34,5842 h60
  text "11" at 9793.09,5722 h60
  text "Bottom Overlay" at 10203,5722 h60
  text ".Layer_Name" at 577,-858.49 h60
M13 Component Bodies Top:
  text ".Layer_Name" at 577,-858.49 h60
M14 Component Bodies Bottom:
  text ".Layer_Name" at 577,-858.49 h60
M15 Courtyards Top:
  text ".Layer_Name" at 577,-858.49 h60
M16 Courtyards Bottom:
  text ".Layer_Name" at 577,-858.49 h60
Drill Drawing:
  circle w10: c1265.55,1093.37 r27.63
  lines w10: 1237.92,872.36 1293.17,872.36 1265.55,817.1 1237.92,872.36 ; 1237.92,941.42 1293.17,941.42 1293.17,996.68 1237.92,996.68 1237.92,941.42 ; 1237.92,1190.06 1265.55,1203.88 1293.17,1190.06 1279.36,1217.69 1293.17,1245.32 1265.55,1231.5 1237.92,1245.32 1251.73,1217.69 1237.92,1190.06
  lines w12: 1187.83,779.81 4419.32,779.81 ; 1187.83,1277.09 4419.32,1277.09 ; 1525.69,655.49 1525.69,1401.41 ; 1857.69,655.49 1857.69,1401.41 ; 2494.26,655.49 2494.26,1401.41 ; 2753.4,655.49 2753.4,1401.41 ; 3128.55,655.49 3128.55,1401.41 ; 3852.88,655.49 3852.88,1401.41 ; 1187.83,655.49 4419.32,655.49 4419.32,1401.41 1187.83,1401.41 1187.83,655.49
  text "Symbol" at 1262.42,1314.38 h72
  text "Quantity" at 1562.99,1314.38 h72
  text "Finished Hole Size" at 1894.99,1314.38 h72
  text "Plated" at 2531.55,1314.38 h72
  text "Hole Type" at 2790.69,1314.38 h72
  text "Drill Layer Pair" at 3165.85,1314.38 h72
  text "Hole Tolerance" at 3890.18,1314.38 h72
  text "192" at 1562.99,1190.06 h60
  text "6.00mil (0.152mm)" at 1894.99,1190.06 h60
  text "PTH" at 2531.55,1190.06 h60
  text "Round" at 2790.69,1190.06 h60
  text "Top Layer - Bottom Layer" at 3165.85,1190.06 h60
  text "22" at 1562.99,1065.74 h60
  text "6.10mil (0.155mm)" at 1894.99,1065.74 h60
  text "PTH" at 2531.55,1065.74 h60
  text "Round" at 2790.69,1065.74 h60
  text "Top Layer - Bottom Layer" at 3165.85,1065.74 h60
  text "1" at 1562.99,941.42 h60
  text "10.00mil (0.254mm)" at 1894.99,941.42 h60
  text "PTH" at 2531.55,941.42 h60
  text "Round" at 2790.69,941.42 h60
  text "Top Layer - Bottom Layer" at 3165.85,941.42 h60
  text "4" at 1562.99,817.1 h60
  text "45.28mil (1.150mm)" at 1894.99,817.1 h60
  text "PTH" at 2531.55,817.1 h60
  text "Round" at 2790.69,817.1 h60
  text "Top Layer - Bottom Layer" at 3165.85,817.1 h60
  text "219 Total" at 1562.99,692.78 h60
  text ".Layer_Name" at 577,-858.49 h60
Mechanical 17:
  text ".Layer_Name" at 577,-858.49 h60
Mechanical 18:
  text ".Layer_Name" at 577,-858.49 h60
Mechanical 19:
  text ".Layer_Name" at 577,-858.49 h60

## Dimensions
0,-400 to 1000,-400 on M2 Board Dimensions
0,0 to 0,852 on M2 Board Dimensions
0,0 to 779,0 on M2 Board Dimensions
